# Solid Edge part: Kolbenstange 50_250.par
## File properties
Username: ahadarics
Dokumentum tartalom típus: 0
Author: ahadarics
Last saved by: ahadarics
Revision: 86
Sűrűség: 0,000 kg/m^3
Pontosság: 0,990
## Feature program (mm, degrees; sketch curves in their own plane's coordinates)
base feature "unnamed BaseFeature 1"
thread "unnamed Thread 1"
chamfer "Letörés_1"  SetBackValue2 = 20 deg
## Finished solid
Body 1: solid body, 21 faces, 32 edges, 14 vertices.
  Faces by surface: plane 8, cylinder 5, cone 4, torus 4
  Edges by curve: circle 17, line 9, curve on surface 4, ellipse 2
Bounding box of the edges (mm; curved faces can reach further): 50.000 x 50.000 x 394.000, from (-25, -25, -86.5) to (25, 25, 307.5).
Cylindrical faces by radius (mm): R6.75 x1, R8 x1, R9.75 x1, R10 x1, R25 x1
Conical faces (half-angle, radius in mm at the cone's reference point): 20 deg R8 x1, 30 deg R9.875 x1, 45 deg R24.25 x1, 60 deg R7.375 x1
Toroidal faces (ring radius, tube radius in mm): R7.15 r0.4 x2, R8.55 r1.2 x2
Planar faces by outward normal: +x 1, +z 3, -x 1, -z 1, oblique 2
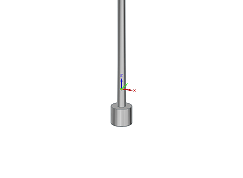
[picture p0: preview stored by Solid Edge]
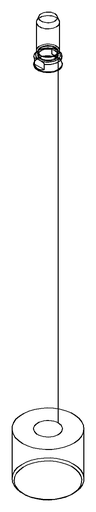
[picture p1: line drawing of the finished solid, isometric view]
